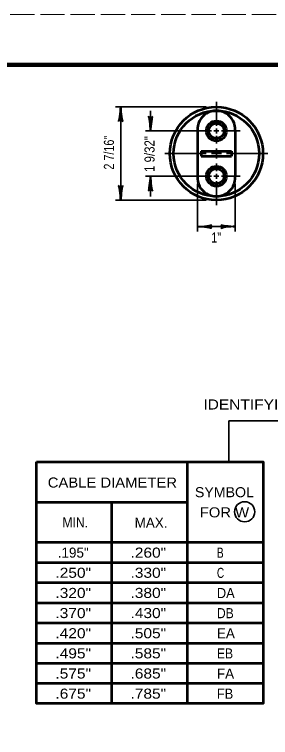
# Model space of a CAD drawing. Extents: x -1 to 679, y 0 to 440.
# Drawn here: x 437.6 to 488.4, y 296.3 to 439.9 of the extents above; entities that cross this region are included whole.
import ezdxf
from ezdxf.enums import TextEntityAlignment as Align

# ---------------------------------------------------------------- set-up
doc = ezdxf.new("R2010")
doc.units = 0
doc.header["$LTSCALE"] = 0.8
doc.linetypes.add('LONG_DASHED', pattern=[7.5, 6, -1.5])
doc.layers.add('1', color=7, linetype='Continuous', lineweight=53)
doc.layers.add('61', color=7, linetype='Continuous', lineweight=35)

msp = doc.modelspace()

# ---------------------------------------------------------------- linework, layer by layer
at = {"layer": '1', "lineweight": 35}
for p, q in [((477.656, 422.5423), (477.656, 417.7923)), ((475.656, 421.5423), (457.656, 421.5423)), ((458.656, 421.5423), (458.656, 403.0423)), ((464.5744, 420.7923), (464.5744, 416.7923)), ((463.5744, 416.7923), (476.656, 416.7923)), ((477.156, 416.7923), (478.156, 416.7923)), ((477.656, 417.2923), (477.656, 416.2923)), ((478.656, 416.7923), (482.406, 416.7923)), ((477.656, 415.7923), (477.656, 414.2923)), ((467.406, 412.2923), (475.656, 412.2923)), ((479.656, 412.2923), (487.906, 412.2923)), ((477.656, 410.2923), (477.656, 408.7923)), ((463.5744, 407.7923), (476.656, 407.7923)), ((464.5744, 407.7923), (464.5744, 403.7923)), ((477.156, 407.7923), (478.156, 407.7923)), ((477.656, 408.2923), (477.656, 407.2923)), ((478.656, 407.7923), (482.406, 407.7923)), ((477.656, 406.7923), (477.656, 402.0423)), ((473.906, 406.2923), (473.906, 396.7923)), ((481.406, 406.2923), (481.406, 396.7923)), ((475.656, 403.0423), (457.656, 403.0423)), ((473.906, 397.7923), (481.406, 397.7923)), ((518.1135, 359.2272), (480.1135, 359.2272)), ((480.1135, 359.2272), (480.1135, 351.2272))]:
    msp.add_line(p, q, dxfattribs=at)
at = {"layer": '1'}
for p, q in [((473.906, 416.7923), (473.906, 412.2923)), ((481.406, 416.7923), (481.406, 412.2923)), ((473.906, 412.2923), (473.906, 407.7923)), ((474.656, 412.7923), (477.656, 412.7923)), ((474.656, 412.7923), (474.656, 411.7923)), ((477.656, 412.7923), (480.656, 412.7923)), ((480.656, 412.7923), (480.656, 411.7923)), ((481.406, 412.2923), (481.406, 407.7923)), ((474.656, 411.7923), (477.656, 411.7923)), ((477.656, 411.7923), (480.656, 411.7923)), ((471.9158, 303.0969), (471.9158, 351.0969)), ((441.9158, 343.0969), (471.9158, 343.0969)), ((456.9158, 303.0969), (456.9158, 343.0969)), ((441.9158, 335.0969), (486.9158, 335.0969)), ((441.9158, 331.0969), (486.9158, 331.0969)), ((441.9158, 327.0969), (486.9158, 327.0969)), ((441.9158, 323.0969), (486.9158, 323.0969)), ((441.9158, 319.0969), (486.9158, 319.0969)), ((441.9158, 315.0969), (486.9158, 315.0969)), ((441.9158, 311.0969), (486.9158, 311.0969)), ((441.9158, 307.0969), (486.9158, 307.0969))]:
    msp.add_line(p, q, dxfattribs=at)
at = {"layer": '1', "lineweight": 35}
for points in [[(476.656, 412.2923), (477.656, 412.2923), (478.656, 412.2923)], [(477.656, 413.2923), (477.656, 412.2923), (477.656, 411.2923)]]:
    msp.add_lwpolyline(points, dxfattribs=at)
at = {"layer": '1'}
msp.add_lwpolyline([(441.9158, 351.0969), (486.9158, 351.0969), (486.9158, 303.0969), (441.9158, 303.0969)], close=True, dxfattribs=at)
for centre, radius in [((477.656, 412.2923), 9.25), ((477.656, 412.2923), 8.5), ((477.656, 416.7923), 2), ((477.656, 416.7923), 1.5), ((477.656, 407.7923), 2), ((477.656, 407.7923), 1.5)]:
    msp.add_circle(centre, radius, dxfattribs=at)
at = {"layer": '1', "lineweight": 35}
msp.add_circle((483.2727, 341.1638), 2, dxfattribs=at)
at = {"layer": '1'}
for centre, start, end in [((477.656, 417.0345), 356.30478, 183.69522), ((477.656, 407.5501), 176.30478, 3.69522)]:
    msp.add_arc(centre, 3.7578, start, end, dxfattribs=at)
at = {"layer": '1', "lineweight": 40}
for centre, major_axis, ratio, start_param, end_param in [((458.4444, 420.4218), (0.1757, 1.7565), 0.07063, 3.14071475, 5.41810995), ((458.4444, 420.4218), (0.1757, 1.7565), 0.07063, 3.14071475, 5.41810995), ((458.9323, 420.4511), (-0.1562, 1.7857), 0.122415, 0.89635335, 3.14159265), ((458.9323, 420.4511), (-0.1562, 1.7857), 0.122415, 0.89635335, 3.14159265), ((464.2981, 417.8835), (0.1562, -1.7857), 0.122415, 0.89635335, 3.14159265), ((464.786, 417.9128), (-0.1757, -1.7565), 0.07063, 3.14071475, 5.41810995), ((464.3628, 406.6718), (0.1757, 1.7565), 0.07063, 3.14071475, 5.41810995), ((464.8507, 406.7011), (-0.1562, 1.7857), 0.122415, 0.89635335, 3.14159265), ((458.3797, 404.1335), (0.1562, -1.7857), 0.122415, 0.89635335, 3.14159265), ((458.8676, 404.1628), (-0.1757, -1.7565), 0.07063, 3.14071475, 5.41810995), ((475.0265, 397.5807), (-1.7565, 0.1757), 0.07063, 3.14071475, 5.41810995), ((475.0265, 397.5807), (-1.7565, 0.1757), 0.07063, 3.14071475, 5.41810995), ((474.9972, 398.0686), (-1.7857, -0.1562), 0.122415, 0.89635335, 3.14159265), ((474.9972, 398.0686), (-1.7857, -0.1562), 0.122415, 0.89635335, 3.14159265), ((480.3148, 397.516), (1.7857, 0.1562), 0.122415, 0.89635335, 3.14159265), ((480.2855, 398.0039), (1.7565, -0.1757), 0.07063, 3.14071475, 5.41810995)]:
    msp.add_ellipse(centre, major_axis=major_axis, ratio=ratio, start_param=start_param, end_param=end_param, dxfattribs=at)
at = {"layer": '61', "linetype": 'LONG_DASHED', "lineweight": 13}
msp.add_line((-1.285, 439.9088), (678.735, 439.9088), dxfattribs=at)
at = {"layer": '61', "lineweight": 158}
msp.add_lwpolyline([(667.755, 429.9088), (28.715, 429.9088), (28.715, 9.8888)], dxfattribs=at)

# ---------------------------------------------------------------- texts
at = {"layer": '1'}
for s, width, p in [('2 7/16"', 0.8, (457.3127, 409.1066)), ('1 9/32"', 0.85, (465.3823, 408.6318))]:
    msp.add_text(s, height=2, rotation=90, dxfattribs=dict(at, width=width)).set_placement(p)
for s, width, p in [('1"', 0.8, (476.6561, 394.6241)), ('IDENTIFYING SYMBOLS III -', 1.15, (475.0802, 361.4665)), ('CABLE DIAMETER', 1.1, (444.1732, 345.9638)), ('MIN.', 0.9, (447.091, 338.0505)), ('B', 0.75, (477.7611, 332.029)), ('C', 0.75, (477.7611, 328.029)), ('DA', 0.95, (477.7611, 324.029)), ('DB', 0.9, (477.7611, 320.029)), ('EB', 0.9, (477.7611, 312.029)), ('FB', 0.95, (477.7611, 304.029))]:
    msp.add_text(s, height=2, dxfattribs=dict(at, width=width)).set_placement(p)
for s, width, p in [('SYMBOL', 1.05, (479.2525, 344.0449)), ('FOR W', 1.1, (479.2524, 340.0449)), ('.260"', 1.15, (464.1443, 332.0457)), ('.250"', 1.15, (449.2307, 328.0457)), ('.330"', 1.15, (464.1443, 328.0457)), ('.320"', 1.15, (449.2307, 324.0457)), ('.380"', 1.15, (464.1443, 324.0457)), ('.370"', 1.15, (449.2307, 320.0457)), ('.430"', 1.15, (464.1443, 320.0457)), ('.420"', 1.15, (449.2307, 316.0457)), ('.505"', 1.15, (464.1443, 316.0457)), ('.495"', 1.15, (449.2307, 312.0457)), ('.585"', 1.15, (464.1443, 312.0457)), ('.575"', 1.15, (449.2307, 308.0457)), ('.685"', 1.15, (464.1443, 308.0457)), ('.675"', 1.15, (449.2307, 304.0457)), ('.785"', 1.15, (464.1443, 304.0457))]:
    msp.add_text(s, height=2, dxfattribs=dict(at, width=width)).set_placement(p, align=Align.CENTER)
for s, p in [('MAX.', (461.421, 337.9857)), ('EA', (477.7611, 316.029)), ('FA', (477.7611, 308.029))]:
    msp.add_text(s, height=2, dxfattribs=at).set_placement(p)
msp.add_text('.195"', height=2, dxfattribs=at).set_placement((449.2308, 332.0457), align=Align.CENTER)

doc.saveas('drawing.dxf')
